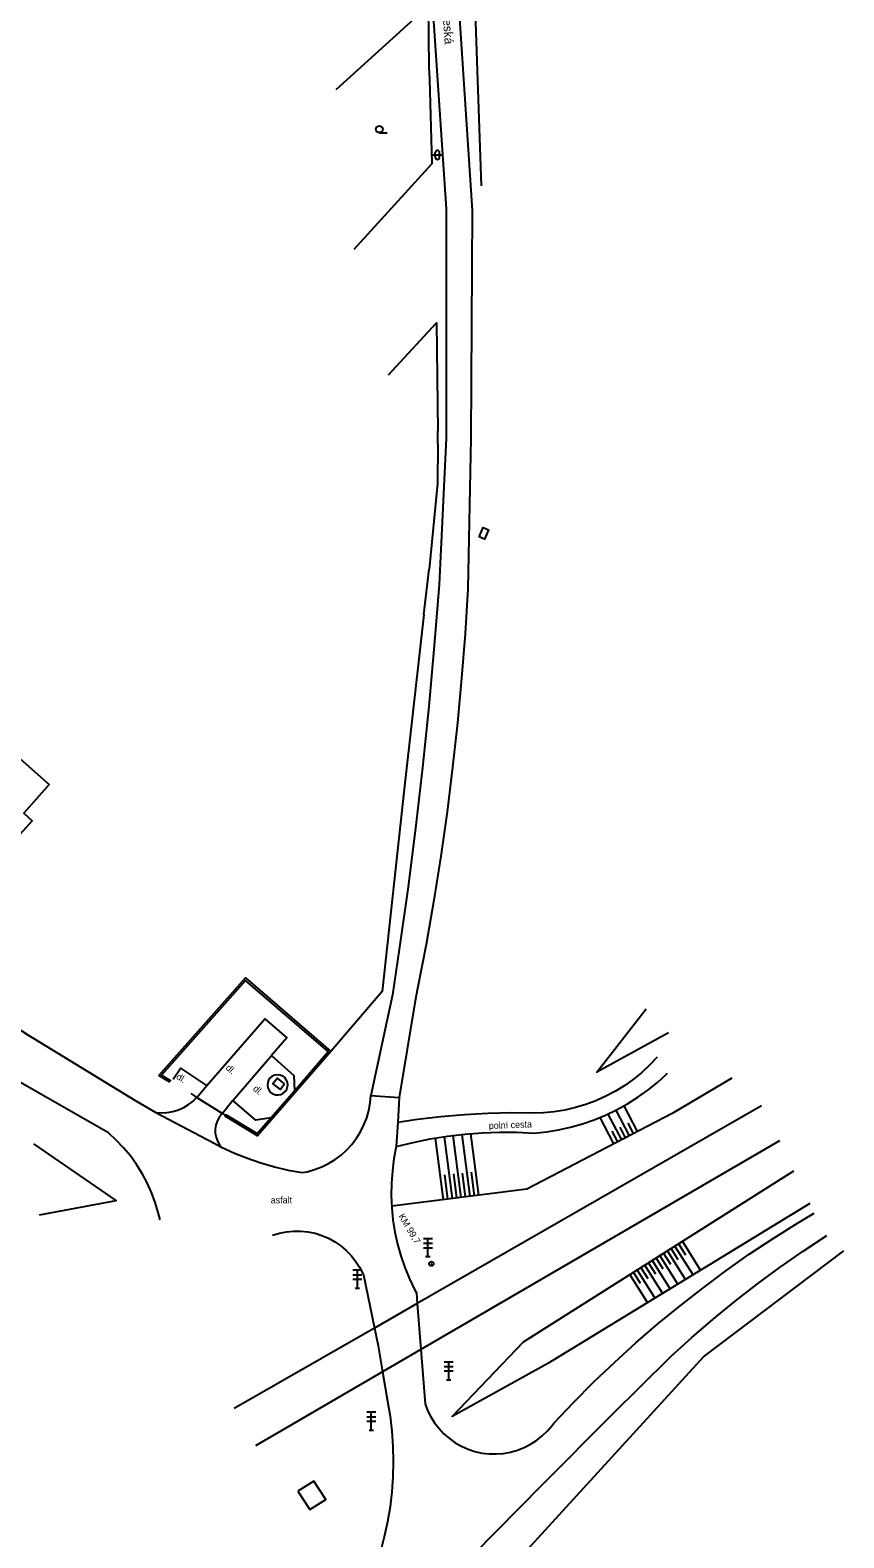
# Model space of a CAD drawing. Extents: x -577457 to -568404, y -1208466 to -1201387.
# Drawn here: x -568750.4 to -568659.1, y -1204488.5 to -1204319.2 of the extents above; entities that cross this region are included whole.
import ezdxf

# ---------------------------------------------------------------- set-up
doc = ezdxf.new("R2010")
doc.units = 0
for name, color, linetype in [('BUDOVY_MĚŘ', 7, 'Continuous'), ('BUDOVY_NEMĚŘ', 7, 'Continuous'), ('NÁZVY_ULIC_TOK_SMĚR', 7, 'Continuous'), ('POMOC_POPIS', 7, 'Continuous'), ('ROZHRANÍ_PLOCH', 7, 'Continuous'), ('VÝŠKOPIS', 7, 'Continuous'), ('ZN_DOPLŇKOVÉ', 7, 'Continuous'), ('ZN_KULTUR', 7, 'Continuous')]:
    doc.layers.add(name, color=color, linetype=linetype)

msp = doc.modelspace()

# ---------------------------------------------------------------- linework, layer by layer
at = {"layer": 'BUDOVY_MĚŘ'}
msp.add_lwpolyline([(-568720.35, -1204483.25), (-568719.02, -1204485.28), (-568717.2, -1204484.16), (-568718.54, -1204482.12), (-568720.35, -1204483.25)], dxfattribs=at)
at = {"layer": 'BUDOVY_NEMĚŘ'}
msp.add_lwpolyline([(-568765.28, -1204406.91), (-568761.04, -1204401.77), (-568756.49, -1204396.62), (-568748.26, -1204403.88), (-568751.11, -1204407.11), (-568750.16, -1204407.95), (-568752.28, -1204410.3), (-568753.2, -1204409.48), (-568756.28, -1204413.1)], dxfattribs=at)
at = {"layer": 'ROZHRANÍ_PLOCH'}
for points in [[(-568702.56, -1204312.14), (-568700.78, -1204339.42)], [(-568705.4, -1204314.25), (-568703.69, -1204339.26)], [(-568703.69, -1204339.26), (-568703.69, -1204365.01), (-568704.48, -1204381.44), (-568705.03, -1204388.29), (-568705.66, -1204395.14), (-568706.37, -1204401.97), (-568707.15, -1204408.8), (-568708.02, -1204415.62), (-568708.97, -1204422.43), (-568709.73, -1204427.5), (-568712.16, -1204438.79)], [(-568700.78, -1204339.42), (-568700.92, -1204364.99), (-568701.26, -1204381.91), (-568701.57, -1204386.93), (-568701.96, -1204391.94), (-568702.43, -1204396.95), (-568702.98, -1204401.95), (-568703.6, -1204406.94), (-568704.31, -1204411.92), (-568705.1, -1204416.89), (-568705.96, -1204421.84), (-568706.91, -1204426.78), (-568707.19, -1204428.19), (-568708.96, -1204439.03)], [(-568700, -1204376.09), (-568699.54, -1204375.03), (-568698.94, -1204375.3), (-568699.41, -1204376.35), (-568700, -1204376.09)], [(-568768.52, -1204420.44), (-568750.54, -1204432.07), (-568750, -1204432.4)], [(-568750, -1204438.2), (-568753.42, -1204436.24), (-568769.88, -1204425.57)], [(-568730.55, -1204437.69), (-568724.05, -1204430.21), (-568721.57, -1204432.35), (-568723.29, -1204434.33)], [(-568750, -1204432.4), (-568738.53, -1204439.42), (-568736.29, -1204440.72)], [(-568727.63, -1204439.38), (-568723.29, -1204434.33)], [(-568723.29, -1204434.33), (-568720.79, -1204436.56), (-568720.74, -1204438.27)], [(-568680, -1204434.49), (-568680.83, -1204435.38), (-568681.72, -1204436.21), (-568682.67, -1204436.98), (-568683.66, -1204437.69), (-568684.69, -1204438.33), (-568685.77, -1204438.9), (-568686.88, -1204439.39), (-568688.02, -1204439.82), (-568689.19, -1204440.17), (-568690.37, -1204440.44), (-568691.58, -1204440.63), (-568692.79, -1204440.75), (-568693.73, -1204440.78), (-568696.37, -1204440.77), (-568699.01, -1204440.84), (-568701.65, -1204440.98), (-568704.28, -1204441.21), (-568706.9, -1204441.52), (-568709.13, -1204441.84)], [(-568730.55, -1204437.69), (-568733.49, -1204435.75), (-568734.34, -1204437.02)], [(-568721.48, -1204437.61), (-568721.52, -1204437.31), (-568721.64, -1204437.03), (-568721.82, -1204436.8), (-568722.07, -1204436.62), (-568722.35, -1204436.51), (-568722.64, -1204436.47), (-568722.94, -1204436.52), (-568723.22, -1204436.64), (-568723.45, -1204436.83), (-568723.63, -1204437.08), (-568723.73, -1204437.36), (-568723.76, -1204437.66), (-568723.7, -1204437.96), (-568723.58, -1204438.23), (-568723.38, -1204438.46), (-568723.13, -1204438.63), (-568722.85, -1204438.73), (-568722.55, -1204438.75), (-568722.25, -1204438.69), (-568721.98, -1204438.55), (-568721.76, -1204438.35), (-568721.59, -1204438.1), (-568721.5, -1204437.81), (-568721.48, -1204437.61)], [(-568721.83, -1204437.5), (-568722.62, -1204436.86), (-568723.14, -1204437.5), (-568722.35, -1204438.14), (-568721.83, -1204437.5)], [(-568709.3, -1204444.53), (-568707.4, -1204444.07), (-568705.48, -1204443.68), (-568703.55, -1204443.37), (-568701.61, -1204443.15), (-568699.66, -1204443), (-568697.71, -1204442.93), (-568695.75, -1204442.94), (-568693.83, -1204443.03), (-568692.45, -1204442.89), (-568691.09, -1204442.67), (-568689.74, -1204442.37), (-568688.4, -1204442), (-568687.1, -1204441.55), (-568685.82, -1204441.02), (-568684.57, -1204440.42), (-568683.36, -1204439.75), (-568682.19, -1204439.01), (-568681.07, -1204438.2), (-568679.99, -1204437.33), (-568678.96, -1204436.4), (-568678.87, -1204436.31)], [(-568735.81, -1204452.78), (-568736.01, -1204451.95), (-568736.35, -1204450.81), (-568736.77, -1204449.69), (-568737.26, -1204448.61), (-568737.82, -1204447.56), (-568738.45, -1204446.55), (-568739.15, -1204445.59), (-568739.91, -1204444.68), (-568740.73, -1204443.81), (-568741.61, -1204443.01), (-568750, -1204438.2)], [(-568736.29, -1204440.72), (-568735.65, -1204440.77), (-568735, -1204440.73), (-568734.37, -1204440.62), (-568733.75, -1204440.43), (-568733.16, -1204440.17), (-568732.61, -1204439.83), (-568732.1, -1204439.43), (-568731.78, -1204439.11), (-568731.7, -1204439.02)], [(-568731.7, -1204439.02), (-568730.55, -1204437.69)], [(-568728.9, -1204444.61), (-568727.46, -1204445.27), (-568725.99, -1204445.86), (-568724.5, -1204446.38), (-568722.97, -1204446.82), (-568721.43, -1204447.19), (-568719.87, -1204447.47), (-568719.3, -1204447.36), (-568718.47, -1204447.13), (-568717.67, -1204446.83), (-568716.9, -1204446.45), (-568716.17, -1204446.01), (-568715.49, -1204445.49), (-568714.85, -1204444.92), (-568714.28, -1204444.29), (-568713.76, -1204443.6), (-568713.31, -1204442.88), (-568712.93, -1204442.11), (-568712.62, -1204441.31), (-568712.39, -1204440.49), (-568712.23, -1204439.64), (-568712.16, -1204438.79)], [(-568712.16, -1204438.79), (-568708.96, -1204439.03)], [(-568708.96, -1204439.03), (-568709.13, -1204441.84)], [(-568736.29, -1204440.72), (-568730.52, -1204443.75), (-568730.31, -1204443.87), (-568728.9, -1204444.61)], [(-568727.63, -1204439.38), (-568728.82, -1204440.81)], [(-568723.37, -1204441.3), (-568725.06, -1204441.56), (-568727.63, -1204439.38)], [(-568728.82, -1204440.81), (-568728.9, -1204440.9), (-568729.19, -1204441.27), (-568729.41, -1204441.68), (-568729.56, -1204442.12), (-568729.63, -1204442.58), (-568729.62, -1204443.04), (-568729.53, -1204443.5), (-568729.36, -1204443.93), (-568729.13, -1204444.34), (-568728.9, -1204444.61)], [(-568709.13, -1204441.84), (-568709.3, -1204444.53)], [(-568709.3, -1204444.53), (-568709.56, -1204445.89), (-568709.74, -1204447.26), (-568709.84, -1204448.64), (-568709.86, -1204450.02), (-568709.8, -1204451.4), (-568709.67, -1204452.77), (-568709.45, -1204454.14), (-568709.15, -1204455.49), (-568708.78, -1204456.82), (-568708.33, -1204458.13), (-568707.8, -1204459.4), (-568707.2, -1204460.65), (-568707.03, -1204460.98), (-568706.94, -1204462.15)], [(-568706.54, -1204467.33), (-568706.07, -1204473.41), (-568705.78, -1204474.17), (-568705.43, -1204474.89), (-568705, -1204475.57), (-568704.5, -1204476.21), (-568703.95, -1204476.8), (-568703.34, -1204477.33), (-568702.68, -1204477.8), (-568701.97, -1204478.19), (-568701.23, -1204478.52), (-568700.47, -1204478.77), (-568699.68, -1204478.95), (-568698.87, -1204479.05), (-568698.07, -1204479.06), (-568697.26, -1204479), (-568696.47, -1204478.86), (-568695.69, -1204478.64), (-568694.94, -1204478.34), (-568694.22, -1204477.97), (-568693.54, -1204477.54), (-568692.91, -1204477.03), (-568692.33, -1204476.47), (-568691.81, -1204475.85), (-568691.62, -1204475.6), (-568689.4, -1204473.26), (-568687.12, -1204470.97), (-568684.78, -1204468.74), (-568682.39, -1204466.57), (-568679.94, -1204464.46), (-568677.45, -1204462.41), (-568674.9, -1204460.43), (-568672.31, -1204458.5), (-568669.67, -1204456.64), (-568666.98, -1204454.85), (-568664.25, -1204453.13), (-568662.4, -1204452.01)], [(-568723.18, -1204454.49), (-568722.41, -1204454.26), (-568721.62, -1204454.1), (-568720.82, -1204454.03), (-568720.01, -1204454.03), (-568719.21, -1204454.12), (-568718.42, -1204454.28), (-568717.65, -1204454.52), (-568716.91, -1204454.84), (-568716.21, -1204455.22), (-568715.54, -1204455.68), (-568714.93, -1204456.2), (-568714.36, -1204456.78), (-568713.86, -1204457.41), (-568713.43, -1204458.09), (-568713.06, -1204458.8), (-568712.99, -1204458.96), (-568711.76, -1204464.92)], [(-568700.65, -1204490.39), (-568692.88, -1204482.48), (-568685.05, -1204474.62), (-568678.59, -1204468.22), (-568678.48, -1204468.12), (-568676.13, -1204465.99), (-568673.73, -1204463.92), (-568671.27, -1204461.91), (-568668.77, -1204459.97), (-568666.21, -1204458.09), (-568663.61, -1204456.27), (-568660.97, -1204454.52)], [(-568706.94, -1204462.15), (-568706.54, -1204467.33)], [(-568711.76, -1204464.92), (-568711.35, -1204466.93), (-568710.85, -1204469.84)], [(-568710.85, -1204469.84), (-568710.28, -1204473.12), (-568710, -1204474.8), (-568709.8, -1204476.5), (-568709.68, -1204478.2), (-568709.64, -1204479.9), (-568709.68, -1204481.61), (-568709.8, -1204483.31), (-568710, -1204485), (-568710.28, -1204486.69), (-568710.64, -1204488.35), (-568711.07, -1204490)]]:
    msp.add_lwpolyline(points, dxfattribs=at)
at = {"layer": 'VÝŠKOPIS'}
for points in [[(-568684.64, -1204440.46), (-568683.15, -1204443.32)], [(-568683.76, -1204439.98), (-568682.26, -1204442.86)], [(-568686.46, -1204441.29), (-568684.92, -1204444.24)], [(-568685.54, -1204440.89), (-568684.03, -1204443.78)], [(-568684.21, -1204442.36), (-568683.59, -1204443.55)], [(-568683.32, -1204441.9), (-568682.7, -1204443.09)], [(-568704.92, -1204443.58), (-568704.04, -1204450.51)], [(-568703.93, -1204443.43), (-568703.04, -1204450.39)], [(-568702.94, -1204443.29), (-568702.05, -1204450.26)], [(-568701.95, -1204443.18), (-568701.06, -1204450.13)], [(-568700.95, -1204443.09), (-568700.07, -1204450.01)], [(-568685.1, -1204442.82), (-568684.48, -1204444.01)], [(-568701.9, -1204447.51), (-568701.56, -1204450.2)], [(-568700.91, -1204447.4), (-568700.56, -1204450.07)], [(-568703.89, -1204447.73), (-568703.54, -1204450.45)], [(-568702.89, -1204447.62), (-568702.55, -1204450.32)], [(-568677.64, -1204457.26), (-568678.45, -1204455.98)], [(-568675.99, -1204458.93), (-568678.03, -1204455.71)], [(-568676.79, -1204456.74), (-568677.61, -1204455.44)], [(-568675.14, -1204458.41), (-568677.18, -1204455.18)], [(-568680.18, -1204458.85), (-568680.99, -1204457.58)], [(-568678.55, -1204460.5), (-568680.56, -1204457.31)], [(-568679.34, -1204458.32), (-568680.14, -1204457.05)], [(-568677.7, -1204459.98), (-568679.72, -1204456.78)], [(-568678.49, -1204457.79), (-568679.3, -1204456.51)], [(-568676.84, -1204459.46), (-568678.87, -1204456.25)], [(-568681.11, -1204462.06), (-568683.1, -1204458.92)], [(-568681.88, -1204459.91), (-568682.68, -1204458.65)], [(-568680.26, -1204461.54), (-568682.26, -1204458.38)], [(-568681.03, -1204459.38), (-568681.83, -1204458.12)], [(-568679.41, -1204461.02), (-568681.41, -1204457.85)]]:
    msp.add_lwpolyline(points, dxfattribs=at)
at = {"layer": 'ZN_DOPLŇKOVÉ'}
for p, q in [((-568705.25, -1204454.9), (-568706.25, -1204454.9)), ((-568706.25, -1204455.4), (-568705.25, -1204455.4)), ((-568706.25, -1204455.9), (-568705.25, -1204455.9)), ((-568705.75, -1204456.9), (-568705.75, -1204454.9)), ((-568706, -1204456.9), (-568705.5, -1204456.9)), ((-568713.16, -1204458.43), (-568714.16, -1204458.43)), ((-568714.16, -1204458.93), (-568713.16, -1204458.93)), ((-568713.66, -1204460.43), (-568713.66, -1204458.43)), ((-568714.16, -1204459.43), (-568713.16, -1204459.43)), ((-568713.91, -1204460.43), (-568713.41, -1204460.43)), ((-568702.91, -1204468.74), (-568703.91, -1204468.74)), ((-568703.91, -1204469.24), (-568702.91, -1204469.24)), ((-568703.41, -1204470.74), (-568703.41, -1204468.74)), ((-568703.91, -1204469.74), (-568702.91, -1204469.74)), ((-568703.66, -1204470.74), (-568703.16, -1204470.74)), ((-568711.6, -1204474.37), (-568712.6, -1204474.37)), ((-568712.1, -1204476.37), (-568712.1, -1204474.37)), ((-568712.6, -1204474.87), (-568711.6, -1204474.87)), ((-568712.6, -1204475.37), (-568711.6, -1204475.37)), ((-568712.35, -1204476.37), (-568711.85, -1204476.37))]:
    msp.add_line(p, q, dxfattribs=at)
for points in [[(-568700.74, -1204308.57), (-568699.78, -1204336.68)], [(-568716.06, -1204325.86), (-568705.69, -1204316.46)], [(-568705.59, -1204323.39), (-568705.69, -1204316.46)], [(-568705.54, -1204324.69), (-568705.59, -1204323.39)], [(-568714.04, -1204343.76), (-568705.28, -1204334.15), (-568705.54, -1204324.69)], [(-568710.17, -1204357.89), (-568704.79, -1204352.06), (-568704.65, -1204364.2)], [(-568704.65, -1204365.65), (-568704.65, -1204364.2)], [(-568704.65, -1204365.65), (-568704.67, -1204370.1), (-568705.59, -1204379.71)], [(-568706.19, -1204384.79), (-568705.59, -1204379.71)], [(-568706.19, -1204384.79), (-568708.42, -1204404.42), (-568710.89, -1204427.12), (-568716.65, -1204433.86)], [(-568734.7, -1204437.32), (-568735.97, -1204436.56), (-568726.24, -1204425.61), (-568716.65, -1204433.86)], [(-568720.74, -1204438.27), (-568716.93, -1204433.88), (-568726.22, -1204425.89), (-568735.66, -1204436.51), (-568734.6, -1204437.15)], [(-568678.75, -1204431.77), (-568686.8, -1204436.17), (-568681.24, -1204429.07)], [(-568716.65, -1204433.86), (-568724.88, -1204443.34), (-568728.5, -1204441.13), (-568728.45, -1204441.04)], [(-568671.62, -1204436.86), (-568678.34, -1204440.81), (-568694.63, -1204449.31), (-568709.81, -1204451.25)], [(-568732.37, -1204438.6), (-568731.7, -1204439.02)], [(-568731.7, -1204439.02), (-568728.82, -1204440.81)], [(-568723.37, -1204441.3), (-568720.74, -1204438.27)], [(-568668.31, -1204439.96), (-568706.94, -1204462.15)], [(-568728.82, -1204440.81), (-568728.45, -1204441.04)], [(-568728.45, -1204441.04), (-568728.4, -1204440.96), (-568724.92, -1204443.08), (-568723.37, -1204441.3)], [(-568666.28, -1204443.9), (-568706.54, -1204467.33)], [(-568749.34, -1204452.2), (-568740.74, -1204450.59), (-568750, -1204444.25)], [(-568662.89, -1204450.94), (-568692.28, -1204468.88), (-568703.03, -1204474.84), (-568695.03, -1204466.47), (-568664.68, -1204447.26)], [(-568821.36, -1204583.4), (-568823.8, -1204579.58), (-568811.46, -1204569.34), (-568781.45, -1204545.27), (-568755.03, -1204528.18), (-568717.8, -1204508.22), (-568698.12, -1204493.66), (-568674.8, -1204468.14), (-568659.06, -1204456.24)], [(-568706.94, -1204462.15), (-568711.76, -1204464.92)], [(-568711.76, -1204464.92), (-568712.8, -1204465.52), (-568727.49, -1204473.94)], [(-568706.54, -1204467.33), (-568710.85, -1204469.84)], [(-568710.85, -1204469.84), (-568725.11, -1204478.14)]]:
    msp.add_lwpolyline(points, dxfattribs=at)
for radius in [0.25, 0.0005]:
    msp.add_circle((-568705.36, -1204457.7), radius, dxfattribs=at)
at = {"layer": 'ZN_KULTUR'}
for p, q in [((-568711.2, -1204330.7), (-568710.33, -1204330.7)), ((-568705.18, -1204333.19), (-568704.18, -1204333.19)), ((-568704.93, -1204333.44), (-568704.93, -1204332.94)), ((-568704.43, -1204333.44), (-568704.43, -1204332.94))]:
    msp.add_line(p, q, dxfattribs=at)
msp.add_circle((-568711.2, -1204330.32), 0.375, dxfattribs=at)
for centre, start, end in [((-568704.68, -1204332.94), 0, 180), ((-568704.68, -1204333.44), 180, 360)]:
    msp.add_arc(centre, 0.25, start, end, dxfattribs=at)

# ---------------------------------------------------------------- texts
at = {"layer": 'NÁZVY_ULIC_TOK_SMĚR'}
msp.add_text('Česká', height=1, rotation=273.9114, dxfattribs=at).set_placement((-568704.12, -1204317.02))
at = {"layer": 'POMOC_POPIS'}
for s, rotation, p in [(' dl.', 318.27, (-568728.73, -1204435.61)), (' dl.', 328.41, (-568734.31, -1204436.74)), (' dl.', 318.27, (-568725.66, -1204437.95)), (' polní cesta', 2.3, (-568699.18, -1204442.59)), ('KM 99,7', 300.72, (-568709.08, -1204452.35))]:
    msp.add_text(s, height=0.75, rotation=rotation, dxfattribs=at).set_placement(p)
msp.add_text(' asfalt', height=0.75, dxfattribs=at).set_placement((-568723.67, -1204450.92))

doc.saveas('drawing.dxf')
